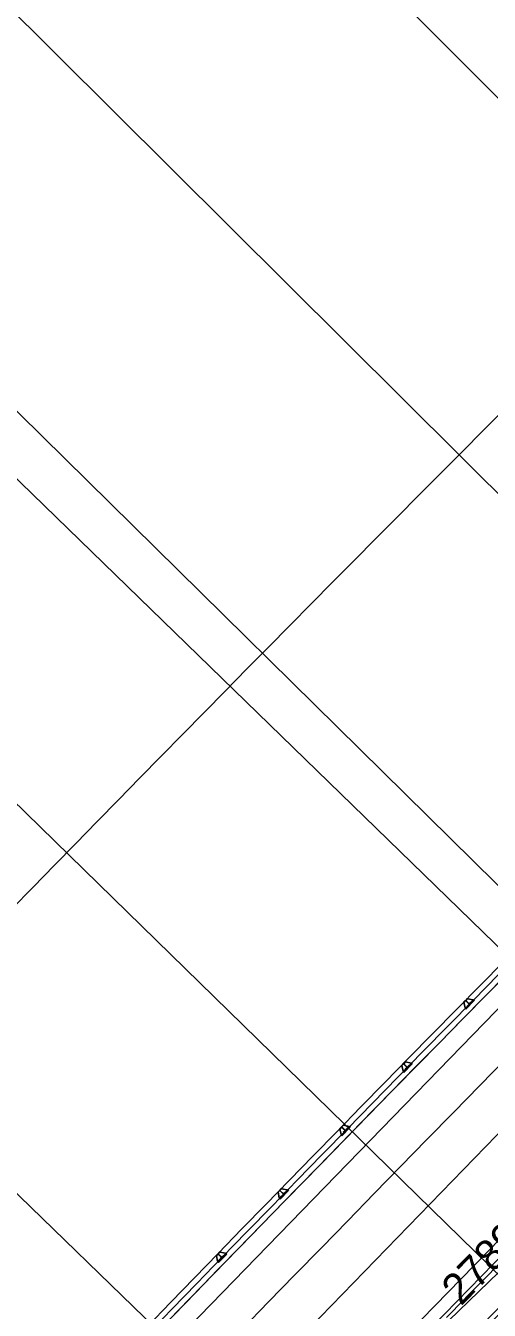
# Model space of a CAD drawing. Extents: x 2376379 to 2383101, y 559608 to 561720.
# Drawn here: x 2377032.2 to 2377074.1, y 561284 to 561400 of the extents above; entities that cross this region are included whole.
import ezdxf

# ---------------------------------------------------------------- set-up
doc = ezdxf.new("R2010")
doc.units = 0
for name, color, linetype in [('BR_X_SV_Bottom_of_Beam', 7, 'Continuous'), ('DT_X_Contour_Minor', 7, 'Continuous'), ('HY_X_Water_Edge', 7, 'Continuous'), ('PM_X_CL_Dashed', 7, 'Continuous'), ('PM_X_CL_Pass_Proh_Lt', 7, 'Continuous'), ('PM_X_Edge_Line', 7, 'Continuous'), ('PM_X_Surveyed_Line', 7, 'Continuous'), ('PV_X_COP', 7, 'Continuous'), ('PV_X_EOP', 7, 'Continuous'), ('PV_X_Shoulder', 7, 'Continuous'), ('RD_X_Cells', 7, 'Continuous'), ('SV_X_Control_Cells_Found', 7, 'Continuous'), ('UT_X_Gas_Cells', 7, 'Continuous')]:
    doc.layers.add(name, color=color, linetype=linetype)

msp = doc.modelspace()

# ---------------------------------------------------------------- linework, layer by layer
at = {"layer": 'BR_X_SV_Bottom_of_Beam'}
for radius in [5724.68, 5713.68]:
    msp.add_arc((2381174.86, 557281.31), radius, 134.05646, 138.41459, dxfattribs=at)
at = {"layer": 'DT_X_Contour_Minor'}
for radius, start, end in [(5786.57, 134.914809, 136.664695), (5672.16, 134.91481, 136.91469)]:
    msp.add_arc((2381174.86, 557281.31), radius, start, end, dxfattribs=at)
at = {"layer": 'HY_X_Water_Edge'}
msp.add_line((2377174.01, 561220.54), (2377012.26, 561377.68), dxfattribs=at)
at = {"layer": 'PM_X_CL_Dashed'}
for radius, start, end in [(5708.5, 134.05646, 138.73479), (5708, 134.78385, 136.87154)]:
    msp.add_arc((2381174.86, 557281.31), radius, start, end, dxfattribs=at)
at = {"layer": 'PM_X_CL_Pass_Proh_Lt'}
for p, q in [((2377071.8, 561311.78), (2377072.15, 561312.13)), ((2377071.82, 561311.76), (2377071.8, 561311.78)), ((2377071.82, 561311.76), (2377071.98, 561311.93)), ((2377071.95, 561311.27), (2377071.83, 561311.78)), ((2377072.16, 561311.43), (2377071.95, 561311.22)), ((2377071.95, 561311.27), (2377071.98, 561311.24)), ((2377071.95, 561311.22), (2377072.01, 561311.16)), ((2377072.31, 561311.61), (2377071.98, 561311.93)), ((2377072, 561311.95), (2377072.17, 561312.12)), ((2377072.32, 561311.63), (2377072, 561311.95)), ((2377072.14, 561311.44), (2377072.31, 561311.61)), ((2377072.16, 561311.43), (2377072.14, 561311.44)), ((2377072.17, 561312.12), (2377072.15, 561312.13)), ((2377072.66, 561312), (2377072.15, 561312.1)), ((2377072.16, 561311.43), (2377072.51, 561311.78)), ((2377072.32, 561311.63), (2377072.49, 561311.8)), ((2377072.51, 561311.78), (2377072.49, 561311.8)), ((2377072.71, 561311.99), (2377072.51, 561311.78)), ((2377072.66, 561312), (2377072.69, 561311.97)), ((2377072.71, 561311.99), (2377072.77, 561311.93)), ((2377066.2, 561306.06), (2377066.55, 561306.42)), ((2377066.21, 561306.05), (2377066.2, 561306.06)), ((2377066.21, 561306.05), (2377066.38, 561306.22)), ((2377066.34, 561305.56), (2377066.23, 561306.07)), ((2377066.34, 561305.56), (2377066.37, 561305.53)), ((2377066.55, 561305.72), (2377066.35, 561305.51)), ((2377066.35, 561305.51), (2377066.41, 561305.45)), ((2377066.71, 561305.9), (2377066.38, 561306.22)), ((2377066.4, 561306.23), (2377066.56, 561306.41)), ((2377066.72, 561305.92), (2377066.4, 561306.23)), ((2377066.54, 561305.73), (2377066.71, 561305.9)), ((2377066.55, 561305.72), (2377066.54, 561305.73)), ((2377066.56, 561306.41), (2377066.55, 561306.42)), ((2377067.06, 561306.29), (2377066.55, 561306.39)), ((2377066.55, 561305.72), (2377066.9, 561306.07)), ((2377066.72, 561305.92), (2377066.89, 561306.09)), ((2377066.9, 561306.07), (2377066.89, 561306.09)), ((2377067.11, 561306.28), (2377066.9, 561306.07)), ((2377067.06, 561306.29), (2377067.09, 561306.26)), ((2377067.11, 561306.28), (2377067.17, 561306.22)), ((2377060.6, 561300.35), (2377060.95, 561300.7)), ((2377060.8, 561300.52), (2377060.97, 561300.69)), ((2377060.97, 561300.69), (2377060.95, 561300.7)), ((2377061.46, 561300.57), (2377060.95, 561300.67)), ((2377060.62, 561300.33), (2377060.6, 561300.35)), ((2377060.62, 561300.33), (2377060.79, 561300.5)), ((2377060.75, 561299.84), (2377060.63, 561300.35)), ((2377060.75, 561299.84), (2377060.78, 561299.81)), ((2377060.96, 561300), (2377060.76, 561299.79)), ((2377060.76, 561299.79), (2377060.82, 561299.73)), ((2377061.11, 561300.18), (2377060.79, 561300.5)), ((2377061.13, 561300.2), (2377060.8, 561300.52)), ((2377060.94, 561300.01), (2377061.11, 561300.18)), ((2377060.96, 561300), (2377060.94, 561300.01)), ((2377060.96, 561300), (2377061.31, 561300.35)), ((2377061.13, 561300.2), (2377061.29, 561300.37)), ((2377061.31, 561300.35), (2377061.29, 561300.37)), ((2377061.51, 561300.56), (2377061.31, 561300.35)), ((2377061.46, 561300.57), (2377061.49, 561300.54)), ((2377061.51, 561300.56), (2377061.57, 561300.5)), ((2377055.02, 561294.62), (2377055.36, 561294.98)), ((2377055.21, 561294.79), (2377055.38, 561294.96)), ((2377055.38, 561294.96), (2377055.36, 561294.98)), ((2377055.87, 561294.84), (2377055.36, 561294.94)), ((2377055.03, 561294.6), (2377055.02, 561294.62)), ((2377055.03, 561294.6), (2377055.2, 561294.77)), ((2377055.16, 561294.11), (2377055.05, 561294.62)), ((2377055.16, 561294.11), (2377055.19, 561294.08)), ((2377055.37, 561294.27), (2377055.17, 561294.06)), ((2377055.17, 561294.06), (2377055.23, 561294)), ((2377055.53, 561294.46), (2377055.2, 561294.77)), ((2377055.54, 561294.47), (2377055.21, 561294.79)), ((2377055.36, 561294.28), (2377055.53, 561294.46)), ((2377055.37, 561294.27), (2377055.36, 561294.28)), ((2377055.37, 561294.27), (2377055.72, 561294.63)), ((2377055.54, 561294.47), (2377055.71, 561294.64)), ((2377055.72, 561294.63), (2377055.71, 561294.64)), ((2377055.93, 561294.84), (2377055.72, 561294.63)), ((2377055.87, 561294.84), (2377055.9, 561294.81)), ((2377055.93, 561294.84), (2377055.99, 561294.78)), ((2377049.44, 561288.88), (2377049.78, 561289.24)), ((2377049.63, 561289.05), (2377049.8, 561289.23)), ((2377049.96, 561288.74), (2377049.63, 561289.05)), ((2377049.8, 561289.23), (2377049.78, 561289.24)), ((2377050.29, 561289.11), (2377049.78, 561289.21)), ((2377050.35, 561289.1), (2377050.14, 561288.89)), ((2377050.29, 561289.11), (2377050.32, 561289.08)), ((2377050.35, 561289.1), (2377050.41, 561289.04)), ((2377049.45, 561288.87), (2377049.44, 561288.88)), ((2377049.45, 561288.87), (2377049.62, 561289.04)), ((2377049.58, 561288.38), (2377049.47, 561288.88)), ((2377049.58, 561288.38), (2377049.61, 561288.35)), ((2377049.79, 561288.53), (2377049.59, 561288.32)), ((2377049.59, 561288.32), (2377049.65, 561288.27)), ((2377049.95, 561288.72), (2377049.62, 561289.04)), ((2377049.78, 561288.55), (2377049.95, 561288.72)), ((2377049.79, 561288.53), (2377049.78, 561288.55)), ((2377049.79, 561288.53), (2377050.14, 561288.89)), ((2377049.96, 561288.74), (2377050.13, 561288.91)), ((2377050.14, 561288.89), (2377050.13, 561288.91))]:
    msp.add_line(p, q, dxfattribs=at)
for points in [[(2377072.77, 561311.93), (2377072.77, 561311.93), (2377072.01, 561311.16)], [(2377067.17, 561306.22), (2377067.17, 561306.22), (2377066.41, 561305.45)], [(2377061.57, 561300.5), (2377061.57, 561300.5), (2377060.82, 561299.73)], [(2377055.99, 561294.78), (2377055.99, 561294.78), (2377055.23, 561294)], [(2377050.41, 561289.04), (2377050.41, 561289.04), (2377049.65, 561288.27)]]:
    msp.add_lwpolyline(points, dxfattribs=at)
for centre, radius, start, end in [((2381174.86, 557281.31), 5750.5, 134.439365, 138.092558), ((2381174.92, 557281.26), 5751.08, 134.791508, 136.863924)]:
    msp.add_arc(centre, radius, start, end, dxfattribs=at)
at = {"layer": 'PM_X_Edge_Line'}
for centre, radius, start, end in [((2381174.86, 557281.31), 5728.92, 134.53962, 137.11495), ((2381174.92, 557281.26), 5750.58, 134.849628, 136.805585), ((2381174.92, 557281.26), 5708.58, 134.84243, 136.81278)]:
    msp.add_arc(centre, radius, start, end, dxfattribs=at)
at = {"layer": 'PM_X_Surveyed_Line'}
for p, q in [((2377044.49, 561423.98), (2377213.94, 561254.02)), ((2377196.65, 561236.7), (2377026.45, 561405.92)), ((2377008.5, 561387.78), (2377179.43, 561219.31)), ((2377162.28, 561201.84), (2376990.62, 561369.56)), ((2376972.82, 561351.27), (2377145.22, 561184.29))]:
    msp.add_line(p, q, dxfattribs=at)
at = {"layer": 'PV_X_COP'}
msp.add_line((2377070.26, 561283.29), (2377078.64, 561291.88), dxfattribs=at)
for radius in [5745.18, 5734.18]:
    msp.add_arc((2381174.86, 557281.31), radius, 134.056462, 138.414594, dxfattribs=at)
at = {"layer": 'PV_X_Shoulder'}
msp.add_arc((2381174.92, 557281.26), 5729.58, 134.852295, 136.802295, dxfattribs=at)
at = {"layer": 'RD_X_Cells'}
msp.add_line((2376995.66, 561210.67), (2377447.66, 561648.02), dxfattribs=at)
msp.add_arc((2381174.86, 557281.31), 5729.93, 134.056462, 139.473129, dxfattribs=at)
msp.add_arc((2381174.86, 557281.31), 5729.93, 134.056462, 139.473129, dxfattribs=at)
at = {"layer": 'SV_X_Control_Cells_Found'}
for radius, start, end in [(5751.58, 134.846062, 136.808529), (5707.58, 134.8385, 136.81609)]:
    msp.add_arc((2381174.92, 557281.26), radius, start, end, dxfattribs=at)
at = {"layer": 'UT_X_Gas_Cells'}
for p, q in [((2377119.53, 561357.12), (2376983.66, 561217.26)), ((2377125.18, 561351.63), (2376989.3, 561211.78)), ((2377130.83, 561346.15), (2376994.95, 561206.29))]:
    msp.add_line(p, q, dxfattribs=at)

# ---------------------------------------------------------------- texts
at = {"layer": 'PV_X_EOP'}
msp.add_text('2789', height=2.8, rotation=45.6648, dxfattribs=at).set_placement((2377071.56, 561284.28))

doc.saveas('drawing.dxf')
